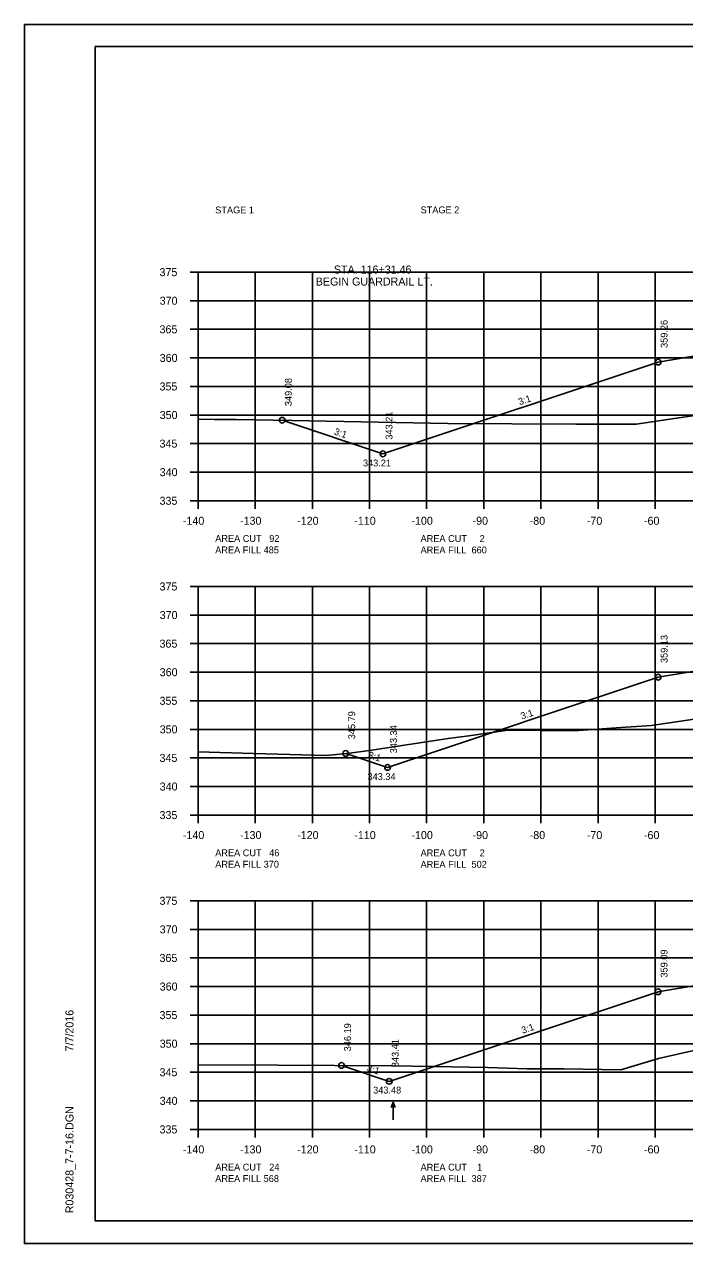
# Model space of a CAD drawing. Extents: x 1374859 to 1376773, y 382242 to 389804.
# Drawn here: x 1376440 to 1376555.6, y 383308.4 to 383521.8 of the extents above; entities that cross this region are included whole.
import ezdxf

# ---------------------------------------------------------------- set-up
doc = ezdxf.new("R2010")
doc.units = 0
for name, color, linetype in [('R_Axis', 7, 'Continuous'), ('R_Axis Annot', 7, 'Continuous'), ('R_Border', 7, 'Continuous'), ('R_Drive', 7, 'Continuous'), ('R_Exist Surface', 7, 'Continuous'), ('R_Fin Surface', 7, 'Continuous'), ('R_Grid', 7, 'Continuous'), ('R_No Plot', 7, 'Continuous'), ('R_Water Annot', 7, 'Continuous'), ('R_Xsect Elev', 7, 'Continuous'), ('R_Xsect Slope', 7, 'Continuous')]:
    doc.layers.add(name, color=color, linetype=linetype)

msp = doc.modelspace()

# ---------------------------------------------------------------- linework, layer by layer
at = {"layer": 'R_Axis'}
for p, q in [((1376469.05, 383478.41), (1376470.45, 383478.41)), ((1376470.45, 383438.41), (1376470.45, 383478.41)), ((1376469.05, 383473.41), (1376470.45, 383473.41)), ((1376469.05, 383468.41), (1376470.45, 383468.41)), ((1376469.05, 383463.41), (1376470.45, 383463.41)), ((1376469.05, 383458.41), (1376470.45, 383458.41)), ((1376469.05, 383453.41), (1376470.45, 383453.41)), ((1376469.05, 383448.41), (1376470.45, 383448.41)), ((1376469.05, 383443.41), (1376470.45, 383443.41)), ((1376469.05, 383438.41), (1376470.45, 383438.41)), ((1376470.45, 383438.41), (1376750.45, 383438.41)), ((1376470.45, 383437.01), (1376470.45, 383438.41)), ((1376480.45, 383437.01), (1376480.45, 383438.41)), ((1376490.45, 383437.01), (1376490.45, 383438.41)), ((1376500.45, 383437.01), (1376500.45, 383438.41)), ((1376510.45, 383437.01), (1376510.45, 383438.41)), ((1376520.45, 383437.01), (1376520.45, 383438.41)), ((1376530.45, 383437.01), (1376530.45, 383438.41)), ((1376540.45, 383437.01), (1376540.45, 383438.41)), ((1376550.45, 383437.01), (1376550.45, 383438.41)), ((1376469.05, 383423.41), (1376470.45, 383423.41)), ((1376470.45, 383383.41), (1376470.45, 383423.41)), ((1376469.05, 383418.41), (1376470.45, 383418.41)), ((1376469.05, 383413.41), (1376470.45, 383413.41)), ((1376469.05, 383408.41), (1376470.45, 383408.41)), ((1376469.05, 383403.41), (1376470.45, 383403.41)), ((1376469.05, 383398.41), (1376470.45, 383398.41)), ((1376469.05, 383393.41), (1376470.45, 383393.41)), ((1376469.05, 383388.41), (1376470.45, 383388.41)), ((1376469.05, 383383.41), (1376470.45, 383383.41)), ((1376470.45, 383383.41), (1376750.45, 383383.41)), ((1376470.45, 383382.01), (1376470.45, 383383.41)), ((1376480.45, 383382.01), (1376480.45, 383383.41)), ((1376490.45, 383382.01), (1376490.45, 383383.41)), ((1376500.45, 383382.01), (1376500.45, 383383.41)), ((1376510.45, 383382.01), (1376510.45, 383383.41)), ((1376520.45, 383382.01), (1376520.45, 383383.41)), ((1376530.45, 383382.01), (1376530.45, 383383.41)), ((1376540.45, 383382.01), (1376540.45, 383383.41)), ((1376550.45, 383382.01), (1376550.45, 383383.41)), ((1376469.05, 383368.41), (1376470.45, 383368.41)), ((1376470.45, 383328.41), (1376470.45, 383368.41)), ((1376469.05, 383363.41), (1376470.45, 383363.41)), ((1376469.05, 383358.41), (1376470.45, 383358.41)), ((1376469.05, 383353.41), (1376470.45, 383353.41)), ((1376469.05, 383348.41), (1376470.45, 383348.41)), ((1376469.05, 383343.41), (1376470.45, 383343.41)), ((1376469.05, 383338.41), (1376470.45, 383338.41)), ((1376469.05, 383333.41), (1376470.45, 383333.41)), ((1376469.05, 383328.41), (1376470.45, 383328.41)), ((1376470.45, 383328.41), (1376750.45, 383328.41)), ((1376470.45, 383327.01), (1376470.45, 383328.41)), ((1376480.45, 383327.01), (1376480.45, 383328.41)), ((1376490.45, 383327.01), (1376490.45, 383328.41)), ((1376500.45, 383327.01), (1376500.45, 383328.41)), ((1376510.45, 383327.01), (1376510.45, 383328.41)), ((1376520.45, 383327.01), (1376520.45, 383328.41)), ((1376530.45, 383327.01), (1376530.45, 383328.41)), ((1376540.45, 383327.01), (1376540.45, 383328.41)), ((1376550.45, 383327.01), (1376550.45, 383328.41))]:
    msp.add_line(p, q, dxfattribs=at)
at = {"layer": 'R_Border'}
for p, q in [((1376452.45, 383517.87), (1376768.63, 383517.87)), ((1376452.45, 383312.41), (1376452.45, 383517.87)), ((1376452.45, 383312.41), (1376452.45, 383312.41)), ((1376768.63, 383312.41), (1376452.45, 383312.41))]:
    msp.add_line(p, q, dxfattribs=at)
at = {"layer": 'R_Exist Surface'}
for points in [[(1376470.45, 383452.67), (1376473.29, 383452.6), (1376477.1, 383452.64), (1376486.87, 383452.46), (1376514.17, 383451.93), (1376536.55, 383451.83), (1376547.15, 383451.83), (1376554.2, 383452.85), (1376563.83, 383454.29)], [(1376470.45, 383394.45), (1376480.14, 383394.16), (1376492.87, 383393.84), (1376496.47, 383394.21), (1376500.47, 383394.71), (1376514.24, 383396.81), (1376517.82, 383397.27), (1376524.69, 383398.28), (1376536.2, 383398.18), (1376543.61, 383398.69), (1376549.83, 383399.1), (1376561.98, 383400.9)], [(1376470.45, 383339.73), (1376484.43, 383339.65), (1376504.28, 383339.51), (1376511.64, 383339.41), (1376521.1, 383339.23), (1376527.97, 383339.02), (1376534.45, 383338.99), (1376544.42, 383338.86), (1376551.01, 383340.81), (1376558.5, 383342.53)]]:
    msp.add_lwpolyline(points, dxfattribs=at)
at = {"layer": 'R_Fin Surface'}
for points in [[(1376485.18, 383452.49), (1376502.81, 383446.62), (1376550.97, 383462.67), (1376558.85, 383463.98), (1376571.04, 383466.02), (1376580.97, 383466.65), (1376610.47, 383468.54), (1376639.97, 383470.43), (1376653.47, 383471.29), (1376669.72, 383468.58), (1376669.97, 383468.54), (1376729.76, 383448.61), (1376731.96, 383449.34)], [(1376496.28, 383394.2), (1376503.61, 383391.75), (1376550.97, 383407.54), (1376562.27, 383409.42), (1376572.97, 383411.21), (1376580.97, 383411.61), (1376610.47, 383413.07), (1376639.97, 383414.54), (1376650.7, 383415.08), (1376664.32, 383412.8), (1376669.97, 383411.86), (1376722.33, 383394.41), (1376725.03, 383395.31)], [(1376495.56, 383339.6), (1376496.1, 383339.42), (1376503.9, 383336.82), (1376506.5, 383337.68), (1376550.95, 383352.5), (1376551.6, 383352.61), (1376562.81, 383354.48)]]:
    msp.add_lwpolyline(points, dxfattribs=at)
at = {"layer": 'R_Grid'}
for p, q in [((1376470.45, 383478.41), (1376750.45, 383478.41)), ((1376470.45, 383438.41), (1376470.45, 383478.41)), ((1376470.45, 383478.41), (1376750.45, 383478.41)), ((1376470.45, 383438.41), (1376470.45, 383478.41)), ((1376480.45, 383438.41), (1376480.45, 383478.41)), ((1376480.45, 383438.41), (1376480.45, 383478.41)), ((1376490.45, 383438.41), (1376490.45, 383478.41)), ((1376490.45, 383438.41), (1376490.45, 383478.41)), ((1376500.45, 383438.41), (1376500.45, 383478.41)), ((1376500.45, 383438.41), (1376500.45, 383478.41)), ((1376510.45, 383438.41), (1376510.45, 383478.41)), ((1376510.45, 383438.41), (1376510.45, 383478.41)), ((1376520.45, 383438.41), (1376520.45, 383478.41)), ((1376520.45, 383438.41), (1376520.45, 383478.41)), ((1376530.45, 383438.41), (1376530.45, 383478.41)), ((1376530.45, 383438.41), (1376530.45, 383478.41)), ((1376540.45, 383438.41), (1376540.45, 383478.41)), ((1376540.45, 383438.41), (1376540.45, 383478.41)), ((1376550.45, 383438.41), (1376550.45, 383478.41)), ((1376550.45, 383438.41), (1376550.45, 383478.41)), ((1376470.45, 383473.41), (1376750.45, 383473.41)), ((1376470.45, 383473.41), (1376750.45, 383473.41)), ((1376470.45, 383468.41), (1376750.45, 383468.41)), ((1376470.45, 383468.41), (1376750.45, 383468.41)), ((1376470.45, 383463.41), (1376750.45, 383463.41)), ((1376470.45, 383463.41), (1376750.45, 383463.41)), ((1376470.45, 383458.41), (1376750.45, 383458.41)), ((1376470.45, 383458.41), (1376750.45, 383458.41)), ((1376470.45, 383453.41), (1376750.45, 383453.41)), ((1376470.45, 383453.41), (1376750.45, 383453.41)), ((1376470.45, 383448.41), (1376750.45, 383448.41)), ((1376470.45, 383448.41), (1376750.45, 383448.41)), ((1376470.45, 383443.41), (1376750.45, 383443.41)), ((1376470.45, 383443.41), (1376750.45, 383443.41)), ((1376470.45, 383438.41), (1376750.45, 383438.41)), ((1376470.45, 383438.41), (1376750.45, 383438.41)), ((1376470.45, 383423.41), (1376750.45, 383423.41)), ((1376470.45, 383383.41), (1376470.45, 383423.41)), ((1376480.45, 383383.41), (1376480.45, 383423.41)), ((1376490.45, 383383.41), (1376490.45, 383423.41)), ((1376500.45, 383383.41), (1376500.45, 383423.41)), ((1376510.45, 383383.41), (1376510.45, 383423.41)), ((1376520.45, 383383.41), (1376520.45, 383423.41)), ((1376530.45, 383383.41), (1376530.45, 383423.41)), ((1376540.45, 383383.41), (1376540.45, 383423.41)), ((1376550.45, 383383.41), (1376550.45, 383423.41)), ((1376470.45, 383418.41), (1376750.45, 383418.41)), ((1376470.45, 383413.41), (1376750.45, 383413.41)), ((1376470.45, 383408.41), (1376750.45, 383408.41)), ((1376470.45, 383403.41), (1376750.45, 383403.41)), ((1376470.45, 383398.41), (1376750.45, 383398.41)), ((1376470.45, 383393.41), (1376750.45, 383393.41)), ((1376470.45, 383388.41), (1376750.45, 383388.41)), ((1376470.45, 383383.41), (1376750.45, 383383.41)), ((1376470.45, 383368.41), (1376750.45, 383368.41)), ((1376470.45, 383328.41), (1376470.45, 383368.41)), ((1376480.45, 383328.41), (1376480.45, 383368.41)), ((1376490.45, 383328.41), (1376490.45, 383368.41)), ((1376500.45, 383328.41), (1376500.45, 383368.41)), ((1376510.45, 383328.41), (1376510.45, 383368.41)), ((1376520.45, 383328.41), (1376520.45, 383368.41)), ((1376530.45, 383328.41), (1376530.45, 383368.41)), ((1376540.45, 383328.41), (1376540.45, 383368.41)), ((1376550.45, 383328.41), (1376550.45, 383368.41)), ((1376470.45, 383363.41), (1376750.45, 383363.41)), ((1376470.45, 383358.41), (1376750.45, 383358.41)), ((1376470.45, 383353.41), (1376750.45, 383353.41)), ((1376470.45, 383348.41), (1376750.45, 383348.41)), ((1376470.45, 383343.41), (1376750.45, 383343.41)), ((1376470.45, 383338.41), (1376750.45, 383338.41)), ((1376470.45, 383333.41), (1376750.45, 383333.41)), ((1376470.45, 383328.41), (1376750.45, 383328.41))]:
    msp.add_line(p, q, dxfattribs=at)
at = {"layer": 'R_No Plot'}
for p, q in [((1376440.05, 383521.76), (1376773.38, 383521.76)), ((1376440.05, 383308.43), (1376773.38, 383308.43))]:
    msp.add_line(p, q, dxfattribs=at)
for points in [[(1376440.04, 383521.76), (1376773.38, 383521.76), (1376773.38, 383308.43), (1376440.04, 383308.43)], [(1376686.37, 383517.87), (1376686.37, 383507.99), (1376722.1, 383507.99), (1376722.1, 383505.07), (1376745.3, 383505.07), (1376745.3, 383480.74), (1376768.63, 383480.74), (1376768.63, 383312.41), (1376452.45, 383312.41), (1376452.45, 383517.87)]]:
    msp.add_lwpolyline(points, close=True, dxfattribs=at)
for centre in [(1376550.97, 383462.67), (1376485.18, 383452.49), (1376502.81, 383446.62), (1376550.97, 383407.54), (1376496.28, 383394.2), (1376503.61, 383391.75), (1376550.95, 383352.5), (1376495.56, 383339.6), (1376503.9, 383336.82)]:
    msp.add_circle(centre, 0.5, dxfattribs=at)
at = {"layer": 'R_Water Annot'}
for p, q in [((1376504.61, 383333.2), (1376504.26, 383332.24)), ((1376504.61, 383330.06), (1376504.61, 383333.2)), ((1376504.61, 383333.2), (1376504.96, 383332.24))]:
    msp.add_line(p, q, dxfattribs=at)

# ---------------------------------------------------------------- texts
at = {"layer": 'R_Axis Annot'}
for s, p in [('STAGE 1', (1376473.45, 383488.69)), ('STAGE 2', (1376509.39, 383488.71))]:
    msp.add_text(s, height=1.2, rotation=360, dxfattribs=at).set_placement(p)
for s, height, p in [('375', 1.4, (1376463.7, 383477.71)), ('370', 1.4, (1376463.73, 383472.71)), ('365', 1.4, (1376463.7, 383467.71)), ('360', 1.4, (1376463.73, 383462.71)), ('355', 1.4, (1376463.7, 383457.71)), ('350', 1.4, (1376463.73, 383452.71)), ('345', 1.4, (1376463.7, 383447.71)), ('340', 1.4, (1376463.73, 383442.71)), ('335', 1.4, (1376463.7, 383437.71)), ('-140', 1.4, (1376467.79, 383434.21)), ('-130', 1.4, (1376477.79, 383434.21)), ('-120', 1.4, (1376487.79, 383434.21)), ('-110', 1.4, (1376497.79, 383434.21)), ('-100', 1.4, (1376507.79, 383434.21)), ('-90', 1.4, (1376518.49, 383434.21)), ('-80', 1.4, (1376528.49, 383434.21)), ('-70', 1.4, (1376538.49, 383434.21)), ('-60', 1.4, (1376548.49, 383434.21)), ('AREA CUT   92', 1.2, (1376473.45, 383431.21)), ('AREA CUT     2', 1.2, (1376509.39, 383431.2)), ('AREA FILL 485', 1.2, (1376473.45, 383429.21)), ('AREA FILL  660', 1.2, (1376509.39, 383429.2)), ('375', 1.4, (1376463.7, 383422.71)), ('370', 1.4, (1376463.73, 383417.71)), ('365', 1.4, (1376463.7, 383412.71)), ('360', 1.4, (1376463.73, 383407.71)), ('355', 1.4, (1376463.7, 383402.71)), ('350', 1.4, (1376463.73, 383397.71)), ('345', 1.4, (1376463.7, 383392.71)), ('340', 1.4, (1376463.73, 383387.71)), ('335', 1.4, (1376463.7, 383382.71)), ('-140', 1.4, (1376467.79, 383379.21)), ('-130', 1.4, (1376477.79, 383379.21)), ('-120', 1.4, (1376487.79, 383379.21)), ('-110', 1.4, (1376497.79, 383379.21)), ('-100', 1.4, (1376507.79, 383379.21)), ('-90', 1.4, (1376518.49, 383379.21)), ('-80', 1.4, (1376528.49, 383379.21)), ('-70', 1.4, (1376538.49, 383379.21)), ('-60', 1.4, (1376548.49, 383379.21)), ('AREA CUT   46', 1.2, (1376473.45, 383376.21)), ('AREA CUT     2', 1.2, (1376509.39, 383376.2)), ('AREA FILL 370', 1.2, (1376473.45, 383374.21)), ('AREA FILL  502', 1.2, (1376509.39, 383374.2)), ('375', 1.4, (1376463.7, 383367.71)), ('370', 1.4, (1376463.73, 383362.71)), ('365', 1.4, (1376463.7, 383357.71)), ('360', 1.4, (1376463.73, 383352.71)), ('355', 1.4, (1376463.7, 383347.71)), ('350', 1.4, (1376463.73, 383342.71)), ('345', 1.4, (1376463.7, 383337.71)), ('340', 1.4, (1376463.73, 383332.71)), ('335', 1.4, (1376463.7, 383327.71)), ('-140', 1.4, (1376467.79, 383324.21)), ('-130', 1.4, (1376477.79, 383324.21)), ('-120', 1.4, (1376487.79, 383324.21)), ('-110', 1.4, (1376497.79, 383324.21)), ('-100', 1.4, (1376507.79, 383324.21)), ('-90', 1.4, (1376518.49, 383324.21)), ('-80', 1.4, (1376528.49, 383324.21)), ('-70', 1.4, (1376538.49, 383324.21)), ('-60', 1.4, (1376548.49, 383324.21)), ('AREA CUT   24', 1.2, (1376473.45, 383321.21)), ('AREA CUT    1', 1.2, (1376509.39, 383321.2)), ('AREA FILL 568', 1.2, (1376473.45, 383319.21)), ('AREA FILL  387', 1.2, (1376509.39, 383319.2))]:
    msp.add_text(s, height=height, dxfattribs=at).set_placement(p)
at = {"layer": 'R_Border'}
for s, p in [('7/7/2016', (1376448.64, 383342.05)), ('R030428_7-7-16.DGN', (1376448.64, 383313.73))]:
    msp.add_text(s, height=1.4, rotation=90, dxfattribs=at).set_placement(p)
at = {"layer": 'R_Drive'}
for s, p in [('STA. 116+31.46', (1376494.22, 383478.17)), ('BEGIN GUARDRAIL LT.', (1376491.04, 383476.07))]:
    msp.add_text(s, height=1.4, dxfattribs=at).set_placement(p)
at = {"layer": 'R_Xsect Elev'}
for s, p in [('359.26', (1376552.62, 383465.15)), ('349.08', (1376486.84, 383454.97)), ('343.21', (1376504.47, 383449.1)), ('359.13', (1376552.62, 383410.02)), ('345.79', (1376497.94, 383396.68)), ('343.34', (1376505.26, 383394.23)), ('359.09', (1376552.61, 383354.98)), ('346.19', (1376497.21, 383342.08)), ('343.41', (1376505.56, 383339.3))]:
    msp.add_text(s, height=1.2, rotation=90, dxfattribs=at).set_placement(p)
for s, p in [('343.21', (1376499.31, 383444.42)), ('343.34', (1376500.11, 383389.55)), ('343.48', (1376501.09, 383334.69))]:
    msp.add_text(s, height=1.2, dxfattribs=at).set_placement(p)
at = {"layer": 'R_Xsect Slope'}
for rotation, p in [(18.4349, (1376526.73, 383455.12)), (341.5651, (1376494.15, 383450.03)), (18.4349, (1376527.13, 383400.12)), (341.5651, (1376500.1, 383393.45)), (18.4351, (1376527.27, 383345.13)), (341.565, (1376499.89, 383338.68))]:
    msp.add_text('3:1', height=1.2, rotation=rotation, dxfattribs=at).set_placement(p)

doc.saveas('drawing.dxf')
